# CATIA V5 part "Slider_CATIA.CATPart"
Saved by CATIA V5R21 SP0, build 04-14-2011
Part number: Slider
Bounding box of the stored display mesh (mm): x -12 to 12, y -12 to 12, z 0 to 10
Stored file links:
  C:\Users\DHARUN\Documents\Codex\2026-11-26\task-2-structural-simulation-fea-perform\outputs\task3_slider_crank\Slider_CATIA.CATPart
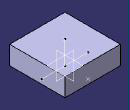
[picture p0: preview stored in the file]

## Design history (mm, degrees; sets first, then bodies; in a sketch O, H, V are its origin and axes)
Set1 "KinematicReferences"
  Point1 "O": (0, 0, 0)
  Point2 "Z": (0, 0, 10)
  Point3 "X": (10, 0, 0)
  Point4 "Y": (0, 10, 0)
  Line1: type PtPt, FirstPoint Point1, SecondPoint Point2
  Plane1: type 3Points, Element1 Point1, Element2 Point3, Element3 Point4
  Point5 "GuideStart": (-10, 0, 0)
  Point6 "GuideEnd": (10, 0, 0)
  Line2: type PtPt, FirstPoint Point5, SecondPoint Point6
  Plane2: type 3Points, Element1 Point1, Element2 Point3, Element3 Point4
Body1 (main body)
  Sketch1 on xy-plane, origin (0, 0, 0), H (1, 0, 0), V (0, 1, 0)
    line L1 (-12, -12) -> (12, -12)
    line L2 (12, -12) -> (12, 12)
    line L3 (12, 12) -> (-12, 12)
    line L4 (-12, 12) -> (-12, -12)
    point P1 (-12, -12)
    point P2 (12, -12)
    point P3 (12, -12)
    point P4 (12, 12)
    point P5 (12, 12)
    point P6 (-12, 12)
    point P7 (-12, 12)
    point P8 (-12, -12)
    coincidence: P1 P8, P2 P3, P4 P5, P6 P7
  Pad1 "Slider_Solid": profile Sketch1, direction (0, 0, 1), length 8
